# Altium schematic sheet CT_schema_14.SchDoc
size 385 x 278 mm
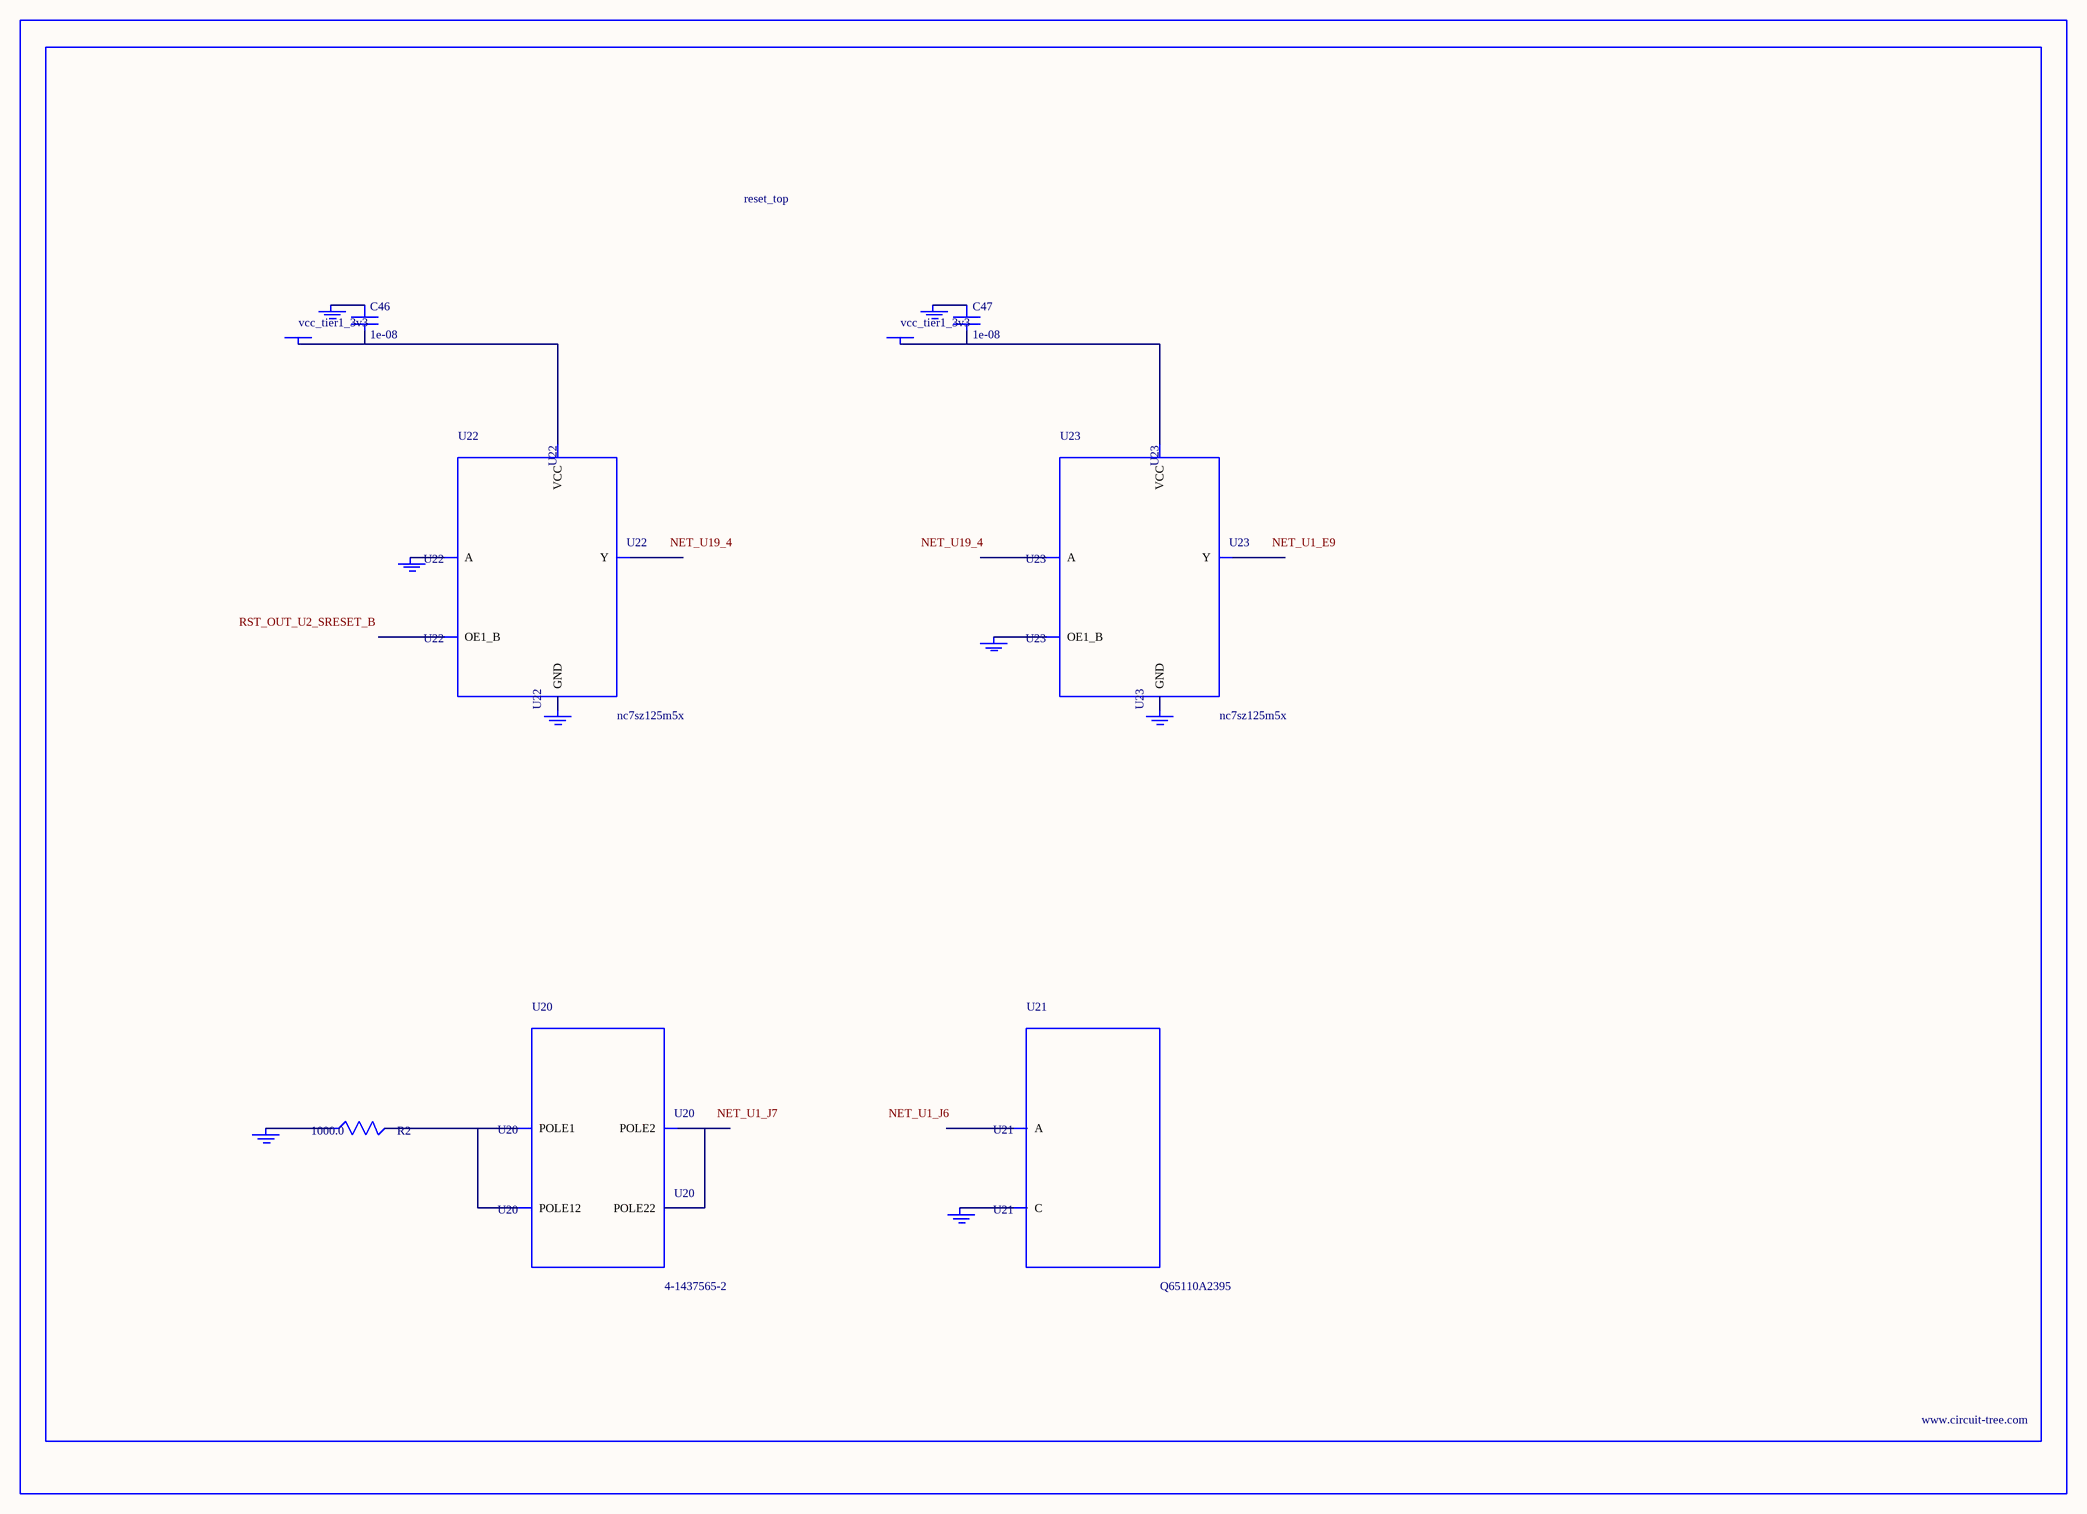
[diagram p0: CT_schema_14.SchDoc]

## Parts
BORDER13  (no value)
C46  1e-08  [C0402]
C47  1e-08  [C0402]
GND_INSTANCE_13_0  (no value)
GND_INSTANCE_13_1  (no value)
GND_INSTANCE_13_2  (no value)
GND_INSTANCE_13_3  (no value)
GND_INSTANCE_13_4  (no value)
GND_INSTANCE_13_5  (no value)
GND_INSTANCE_13_6  (no value)
GND_INSTANCE_13_7  (no value)
POWER_INSTANCE_13_0  vcc_tier1_3v3
POWER_INSTANCE_13_1  vcc_tier1_3v3
R2  1000.0  [R0603]
U20  4-1437565-2  [SW_4-1437565-2]
U21  Q65110A2395  [LGM67K-G1J2-24-Z]
U22  nc7sz125m5x  [NC7SZ125M5X]
U23  nc7sz125m5x  [NC7SZ125M5X]

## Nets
NetC46_1: C46.1 GND_INSTANCE_13_2.0(GND)
NetC46_2: C46.2 POWER_INSTANCE_13_0.0(PWR) U22.5(VCC)
NetC47_1: C47.1 GND_INSTANCE_13_5.0(GND)
NetC47_2: C47.2 POWER_INSTANCE_13_1.0(PWR) U23.5(VCC)
NetGND_INSTANCE_13_0_0: GND_INSTANCE_13_0.0(GND) R2.1
NetGND_INSTANCE_13_1_0: GND_INSTANCE_13_1.0(GND) U21.C
NetGND_INSTANCE_13_3_0: GND_INSTANCE_13_3.0(GND) U22.2(A)
NetGND_INSTANCE_13_4_0: GND_INSTANCE_13_4.0(GND) U22.3(GND)
NetGND_INSTANCE_13_6_0: GND_INSTANCE_13_6.0(GND) U23.1(OE1_B)
NetGND_INSTANCE_13_7_0: GND_INSTANCE_13_7.0(GND) U23.3(GND)
NetR2_2: R2.2 U20.1(POLE1) U20.2(POLE12)
NetU20_3: U20.3(POLE2) U20.4(POLE22)

Not connected (* = marked no-connect by the designer): U21 A; U22 1(OE1_B) 4(Y); U23 2(A) 4(Y)

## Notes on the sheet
- Labels drawn without touching a wire or pin: NET_U1_E9, NET_U1_J6, NET_U1_J7, NET_U19_4, RST_OUT_U2_SRESET_B

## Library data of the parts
BORDER13 = BORDER_PAGE13
C46 C47 = C0402C103K3RAC
GND_INSTANCE_13_0-GND_INSTANCE_13_7 = GND
POWER_INSTANCE_13_0 POWER_INSTANCE_13_1 = PWR
R2 = RC0603JR-071KL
